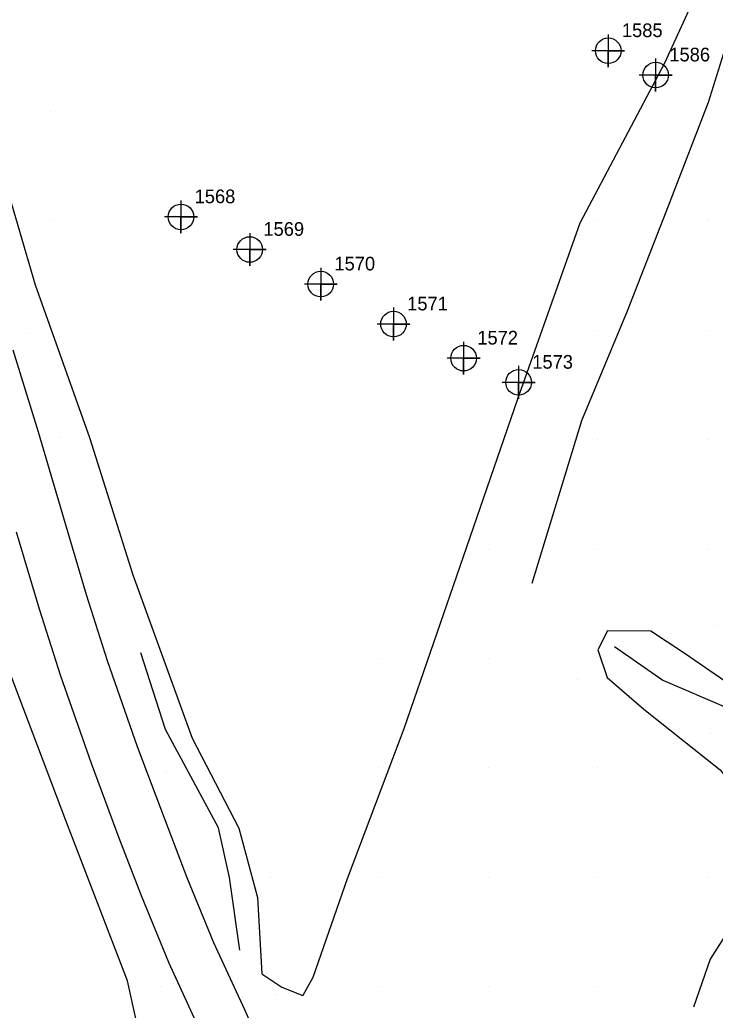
# Model space of a CAD drawing. Extents: x 2062781 to 2066835, y 358981 to 366501.
# Drawn here: x 2063909.5 to 2064036.6, y 361471.1 to 361652.2 of the extents above; entities that cross this region are included whole.
import ezdxf

# ---------------------------------------------------------------- set-up
doc = ezdxf.new("R2010")
doc.units = 0
for name, color, linetype in [('Exist DTM Regular Point CELL', 7, 'Continuous'), ('Exist DTM Regular Point Cogo Number', 7, 'Continuous'), ('PH Exist DTM Breakline', 7, 'Continuous'), ('PH Exist DTM Point', 7, 'Continuous')]:
    doc.layers.add(name, color=color, linetype=linetype)

msp = doc.modelspace()

# ---------------------------------------------------------------- linework, layer by layer
at = {"layer": 'Exist DTM Regular Point CELL'}
for points in [[(2064017.03, 361649.49), (2064017.03, 361643.49), (2064017.03, 361646.49), (2064020.03, 361646.49), (2064014.03, 361646.49)], [(2064025.7, 361645.05), (2064025.7, 361639.05), (2064025.7, 361642.05), (2064028.7, 361642.05), (2064022.7, 361642.05)], [(2063938.94, 361619.12), (2063938.94, 361613.12), (2063938.94, 361616.12), (2063941.94, 361616.12), (2063935.94, 361616.12)], [(2063951.51, 361613.16), (2063951.51, 361607.16), (2063951.51, 361610.16), (2063954.51, 361610.16), (2063948.51, 361610.16)], [(2063964.49, 361606.83), (2063964.49, 361600.83), (2063964.49, 361603.83), (2063967.49, 361603.83), (2063961.49, 361603.83)], [(2063977.79, 361599.53), (2063977.79, 361593.53), (2063977.79, 361596.53), (2063980.79, 361596.53), (2063974.79, 361596.53)], [(2063990.6, 361593.29), (2063990.6, 361587.29), (2063990.6, 361590.29), (2063993.6, 361590.29), (2063987.6, 361590.29)], [(2064000.65, 361588.87), (2064000.65, 361582.87), (2064000.65, 361585.87), (2064003.65, 361585.87), (2063997.65, 361585.87)]]:
    msp.add_lwpolyline(points, dxfattribs=at)
for centre in [(2064017.03, 361646.49), (2064025.7, 361642.05), (2063938.94, 361616.12), (2063951.51, 361610.16), (2063964.49, 361603.83), (2063977.79, 361596.53), (2063990.6, 361590.29), (2064000.65, 361585.87)]:
    msp.add_circle(centre, 2.34, dxfattribs=at)
at = {"layer": 'PH Exist DTM Breakline'}
for points in [[(2064003.15, 361549.18), (2064012.19, 361578.87), (2064020.56, 361598.92), (2064028.03, 361618.12), (2064035.38, 361637.08), (2064039, 361648.8), (2064044.56, 361664.53), (2064049.31, 361675.12), (2064057.21, 361696.49), (2064060.52, 361703.85), (2064065.71, 361709.1), (2064070.09, 361711.76), (2064076.43, 361719.47), (2064080.12, 361731.76), (2064084.81, 361744.46)], [(2063953.7, 361477.72), (2063957.4, 361475.32), (2063961.2, 361473.79), (2063961.3, 361473.83), (2063963.13, 361477.13), (2063969.36, 361495.18), (2063979.74, 361522.57), (2063990.6, 361554.02), (2064000.48, 361582.84), (2064011.9, 361615.02), (2064027.39, 361644.29), (2064037.61, 361666.64), (2064048.96, 361690.76), (2064057.83, 361709.5), (2064071.48, 361736.61)], [(2063893.38, 361700.7), (2063894.25, 361681.32), (2063900.33, 361651.45), (2063905.06, 361628.32), (2063912.27, 361603.71), (2063922.23, 361575.78), (2063930.13, 361550.66), (2063941, 361520.81), (2063949.54, 361504.35), (2063952.94, 361491.7), (2063953.7, 361477.72)], [(2063821.11, 361247.46), (2063835.72, 361263.54), (2063847.51, 361286.69), (2063858.07, 361307.99), (2063864.46, 361320.81), (2063871.42, 361333.91), (2063881.17, 361349.79), (2063889.24, 361365.38), (2063891.81, 361375.48), (2063902.17, 361385.33), (2063911.66, 361395.03), (2063916.81, 361402.12), (2063920.03, 361420.56), (2063920.06, 361434.43), (2063929.36, 361438.03), (2063936.26, 361445.41), (2063934.09, 361454.14), (2063929.19, 361476.47), (2063917.89, 361505.78), (2063905.97, 361537.31), (2063894.18, 361565.53), (2063885.56, 361601.66), (2063876.23, 361640.09), (2063869.62, 361677.18)], [(2064136.92, 361676.99), (2064126.8, 361656.82), (2064107.83, 361619.93), (2064089.29, 361582.58), (2064082.28, 361560.59), (2064074.31, 361544.79), (2064064.84, 361529.6), (2064060.63, 361527.17), (2064052.5, 361528.16), (2064038.54, 361531.11), (2064030.93, 361536.34), (2064024.8, 361540.38), (2064016.9, 361540.46), (2064015.15, 361536.98), (2064016.86, 361531.89), (2064023.56, 361526.11), (2064037.46, 361515.03), (2064043.13, 361507.62), (2064047.86, 361501.15), (2064040.76, 361488.48), (2064035.68, 361480.43), (2064032.63, 361471.63)], [(2063989.12, 361404.75), (2063987.67, 361406.81), (2063982.75, 361413.54), (2063976.73, 361421.95), (2063972.28, 361428.26), (2063968.24, 361434.84), (2063965.22, 361440.26), (2063960.78, 361448.72), (2063955.78, 361459.58), (2063950.6, 361471.18), (2063944.95, 361483.41), (2063940.09, 361495.29), (2063936.09, 361505.72), (2063931.02, 361519.26), (2063925.52, 361534.99), (2063921.69, 361547.04), (2063917.51, 361561.05), (2063912.91, 361576.74), (2063908.26, 361591.78)], [(2063991.93, 361384.95), (2063987.48, 361391.38), (2063983.72, 361396.8), (2063980.36, 361401.56), (2063975.46, 361408.26), (2063969.4, 361416.74), (2063964.76, 361423.3), (2063960.47, 361430.29), (2063957.3, 361435.98), (2063952.7, 361444.75), (2063947.58, 361455.86), (2063942.41, 361467.46), (2063936.7, 361479.82), (2063931.72, 361491.97), (2063927.67, 361502.53), (2063922.56, 361516.19), (2063916.98, 361532.14), (2063913.09, 361544.39), (2063908.88, 361558.49)], [(2064018.19, 361537.61), (2064027.02, 361531.41), (2064038.67, 361526.43), (2064050.98, 361520.88), (2064055.67, 361518.99), (2064060.43, 361518.99), (2064065.37, 361521.62), (2064071.02, 361528.52)], [(2063949.68, 361482.05), (2063947.8, 361495.34), (2063945.82, 361504.43), (2063936.09, 361522.39), (2063931.58, 361536.4)]]:
    msp.add_lwpolyline(points, dxfattribs=at)
at = {"layer": 'PH Exist DTM Point'}
for p, q in [((2063915.13, 361635.38), (2063915.13, 361635.38)), ((2063915.13, 361615.38), (2063915.13, 361615.38)), ((2064015.13, 361615.38), (2064015.13, 361615.38)), ((2064035.13, 361615.38), (2064035.13, 361615.38)), ((2064015.13, 361595.38), (2064015.13, 361595.38)), ((2064035.08, 361595.38), (2064035.08, 361595.38)), ((2063911.3, 361594.81), (2063911.3, 361594.81)), ((2063916.77, 361575.79), (2063916.77, 361575.79)), ((2064015.13, 361575.38), (2064015.13, 361575.38)), ((2064035.12, 361575.36), (2064035.12, 361575.36)), ((2063995.11, 361555.4), (2063995.11, 361555.4)), ((2064015.11, 361555.4), (2064015.11, 361555.4)), ((2064035.13, 361555.38), (2064035.13, 361555.38)), ((2064036.5, 361541.38), (2064036.5, 361541.38)), ((2063975.13, 361535.38), (2063975.13, 361535.38)), ((2063995.15, 361535.37), (2063995.15, 361535.37)), ((2064011.4, 361531.53), (2064011.4, 361531.53)), ((2064035.75, 361521.69), (2064035.75, 361521.69)), ((2063936.33, 361514.76), (2063936.33, 361514.76)), ((2063975.13, 361515.38), (2063975.13, 361515.38)), ((2063995.11, 361515.4), (2063995.11, 361515.4)), ((2064015.11, 361515.4), (2064015.11, 361515.4)), ((2063955.23, 361495.31), (2063955.23, 361495.31)), ((2063975.13, 361495.38), (2063975.13, 361495.38)), ((2063995.11, 361495.4), (2063995.11, 361495.4)), ((2064015.13, 361495.38), (2064015.13, 361495.38)), ((2064035.13, 361495.38), (2064035.13, 361495.38)), ((2063935.13, 361475.38), (2063935.13, 361475.38)), ((2063975.13, 361475.38), (2063975.13, 361475.38)), ((2063995.13, 361475.38), (2063995.13, 361475.38)), ((2064015.13, 361475.38), (2064015.13, 361475.38)), ((2063956.3, 361473.89), (2063956.3, 361473.89))]:
    msp.add_line(p, q, dxfattribs=at)

# ---------------------------------------------------------------- texts
at = {"layer": 'Exist DTM Regular Point Cogo Number'}
for s, p in [('1585', (2064019.53, 361648.99)), ('1585', (2064019.53, 361648.99)), ('1585', (2064019.53, 361648.99)), ('1586', (2064028.2, 361644.55)), ('1586', (2064028.2, 361644.55)), ('1586', (2064028.2, 361644.55)), ('1568', (2063941.44, 361618.62)), ('1568', (2063941.44, 361618.62)), ('1568', (2063941.44, 361618.62)), ('1569', (2063954.01, 361612.66)), ('1569', (2063954.01, 361612.66)), ('1569', (2063954.01, 361612.66)), ('1570', (2063966.99, 361606.33)), ('1570', (2063966.99, 361606.33)), ('1570', (2063966.99, 361606.33)), ('1571', (2063980.29, 361599.03)), ('1571', (2063980.29, 361599.03)), ('1571', (2063980.29, 361599.03)), ('1572', (2063993.1, 361592.79)), ('1572', (2063993.1, 361592.79)), ('1572', (2063993.1, 361592.79)), ('1573', (2064003.15, 361588.37)), ('1573', (2064003.15, 361588.37)), ('1573', (2064003.15, 361588.37))]:
    msp.add_text(s, height=2.5, dxfattribs=at).set_placement(p)

doc.saveas('drawing.dxf')
